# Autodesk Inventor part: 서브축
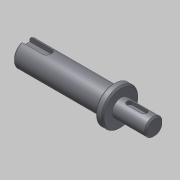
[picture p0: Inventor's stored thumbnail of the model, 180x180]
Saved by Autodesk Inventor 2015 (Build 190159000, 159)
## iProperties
Created: 2018-09
Part Number: 서브축
Document SubType Name: Modeling
Density: 1 g/cm^3
Material: 강철, 연강
Appearance: 강철
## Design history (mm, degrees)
sketch "스케치1"
  geometry: L1 (-18.818, -7)-(-18.818, 7) reference; L2 (-41.331, -13.5)-(-41.331, 13.5) reference; L3 (-46.5, 12.249)-(-46.5, -12.249) reference; L4 (-18.331, 0)-(-106.5, 0); L5 (-18.331, 0)-(-18.331, -6); L6 (-18.331, -6)-(-41.331, -6); L7 (-41.331, -12.5)-(-46.5, -12.5); L8 (-46.5, -8.5)-(-106.5, -8.5); L9 (-106.5, -8.5)-(-106.5, 0); L10 (-46.5, -8.5)-(-46.5, -12.5); L11 (-41.331, -6)-(-41.331, -12.5); 2 further points
  constraints: 17 end point, 5 point on line, 3 parallel, 3 perpendicular, 2 collinear, 1 midpoint
  dimensions: "d0" = 23 distance between parallel lines of L2 L5; "d1" = 12 diameter of L6 L4; "d2" = 25 diameter of L7 L4; "d3" = 17 diameter of L8 L4; "d4" = 60 distance of L8.start L8.end
revolve "회전1" sketch "스케치1" stored, may be unused: angle "d5" = 90 deg
chamfer "모따기1" distance "d6" = 1; stored, may be unused: second distance "d7" = 2, angle "d8" = 45 deg
node "작업 평면1"
sketch "스케치2"
  geometry: L1 (11.5, 5)-(11.5, -5) reference; L2 (-5.5, -2)-(4.5, -2); L3 (4.5, 2)-(-5.5, 2); A1 r 2 centre (4.5, 0) between (4.5, -2) and (4.5, 2); A2 r 2 centre (-5.5, 0) between (-5.5, 2) and (-5.5, -2); 2 further points
  constraints: 4 end point, 4 point on circle, 4 tangent, 2 centre point, 1 horizontal alignment, 1 midpoint, 1 parallel, 1 perpendicular
  dimensions: "d9" = 4 distance between parallel lines of L2 L3; "d10" = 14 dimension on A1 A2; "d11" = 5 distance edge to line of A1 L1
extrude "돌출1" cut sketch "스케치2" distance "d12" = 2.5; taper "d13" = 0 deg
node "작업 평면2"
sketch "스케치3"
  geometry: L1 (-30, -7.5)-(-30, 7.5) reference; L2 (-30, 3)-(-15, 3); L3 (-15, -3)-(-30, -3); A1 r 3 centre (-15, 0) between (-15, -3) and (-15, 3); 2 further points
  constraints: 4 end point, 2 perpendicular, 2 point on circle, 2 point on line, 2 tangent, 1 centre point, 1 horizontal alignment, 1 midpoint
  dimensions: "d14" = 6 distance between parallel lines of L3 L2; "d15" = 18 dimension on A1 L1
extrude "돌출2" cut sketch "스케치3" distance "d16" = 3.5; taper "d17" = 0 deg
node "솔리드1"
node "참조1"
node "참조2"
node "참조3"
